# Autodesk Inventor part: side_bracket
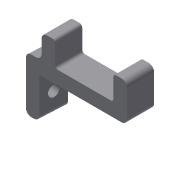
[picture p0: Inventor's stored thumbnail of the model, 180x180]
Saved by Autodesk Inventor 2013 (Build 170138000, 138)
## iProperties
Created: 2013-11
Part Number: side_bracket
Material: Generic
Document SubType Name: Modeling
Designer: Jonas
Density: 1 g/cm^3
d0: 87,00 deg
d1: 36,741 mm
d7: 10,000 mm
d8: 5,000 mm
d9: 0,00 deg
d10: 5,000 mm
d11: 5,000 mm
d12: 21,500 mm
d13: 9,000 mm
d14: 0,00 deg
d18: 5,000 mm
d19: 15,000 mm
d20: 0,00 deg
d21: 4,000 mm
d28: 2,000 mm
d29: 1,000 mm
theta: 3,00 deg
frame_height: 710,000 mm
clearance_top: 400,000 mm
clearance_side: 250,000 mm
side_bracket_padding_top: 100,000 mm
sprocket_N: 18,000 ul
sprocket_wall_clearance: 1,000 mm
ball_diameter: 2,400 mm
ball_distance: 0,820 mm
frame_thickness: 21,500 mm
Author: Jonas
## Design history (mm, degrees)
sketch "Sketch1"
  geometry: L1 (0, 0)-(37.265, 0); L2 (37.265, 0)-(37.265, 10); L3 (37.265, 10)-(0.524, 10); L4 (0.524, 10)-(0, 0)
  constraints: 8 end point, 1 horizontal, 1 parallel, 1 perpendicular
  dimensions: "d0" = 87 deg angle of L1 L4 (computed from theta); "d1" = 36.74078 distance of L2.end L3.end (computed from frame_thickness, side_bracket_padding_top, theta); "d7" = 10 distance of L1.end L2.end
extrude "Extrusion1" new body sketch "Sketch1" distance "d8" = 5; taper "d9" = 0 deg
sketch "Sketch4"
  geometry: L1 (0, 0)-(37.265, 0) reference; L2 (37.265, 10)-(0.524, 10) reference; L3 (37.265, 10)-(32.265, 10); L4 (32.265, 10)-(32.265, 0); L5 (32.265, 0)-(37.265, 0); L6 (37.265, 0)-(37.265, 10); L7 (10.765, 10)-(5.765, 10); L8 (5.765, 10)-(5.765, 0); L9 (5.765, 0)-(10.765, 0); L10 (10.765, 0)-(10.765, 10)
  constraints: 16 end point, 4 parallel, 3 point on line, 2 horizontal, 2 perpendicular
  dimensions: "d10" = 5 distance of L5.end L4.end; "d11" = 5 distance of L9.end L8.end; "d12" = 21.5 distance between parallel lines of L4 L10 (= frame_thickness)
extrude "Extrusion2" join sketch "Sketch4" distance "d13" = 9; taper "d14" = 0 deg
sketch "Sketch6"
  geometry: L1 (0, 0)-(-37.265, 0) reference; L2 (-0.524, 10)-(0, 0) reference; L3 (-37.265, 10)-(-0.524, 10) reference; L4 (0, 0)-(-5, 0); L5 (-5, 0)-(-5.524, 10); L6 (-0.524, 10)-(0, 0)
  constraints: 6 end point, 2 equal length, 2 point on line
  dimensions: "d18" = 5 distance of L1.start L4.end
extrude "Extrusion4" join sketch "Sketch6" distance "d19" = 15; taper "d20" = 0 deg
sketch "Sketch7"
  geometry: L1 (0, 10.014)-(15, 0); 2 further points
  constraints: 2 end point, 1 midpoint
hole "Hole1" sketch "Sketch7" at (7.5, 5.007) diameter "d21" = 4; stored, may be unused: countersink angle "d25" = 90 deg, drill point angle "d27" = 118 deg; dims "d22" = 6, "d23" = 4, "d24" = 2, "d26" = 8
fillet "Fillet1" dims "d28" = 2
fillet "Fillet2" dims "d29" = 1
body "Solid1"
other parameters: "theta" = 3 deg, "frame_height" = 710, "clearance_top" = 400, "clearance_side" = 250, "side_bracket_padding_top" = 100, "sprocket_N" = 18, "sprocket_wall_clearance" = 1, "ball_diameter" = 2.4, "ball_distance" = 0.82, "frame_thickness" = 21.5
